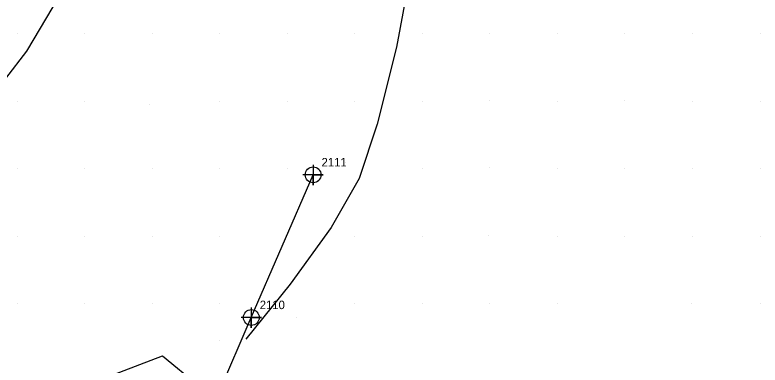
# Model space of a CAD drawing. Extents: x 2062781 to 2066835, y 358981 to 366501.
# Drawn here: x 2064250 to 2064470.6, y 361652.2 to 361755.8 of the extents above; entities that cross this region are included whole.
import ezdxf

# ---------------------------------------------------------------- set-up
doc = ezdxf.new("R2010")
doc.units = 0
for name, color, linetype in [('Exist DTM Breakline', 7, 'Continuous'), ('Exist DTM Breakline Cogo Number', 7, 'Continuous'), ('Exist DTM Breakline Cogo Point CELL', 7, 'Continuous'), ('PH Exist DTM Breakline', 7, 'Continuous'), ('PH Exist DTM Point', 7, 'Continuous')]:
    doc.layers.add(name, color=color, linetype=linetype)

msp = doc.modelspace()

# ---------------------------------------------------------------- linework, layer by layer
at = {"layer": 'Exist DTM Breakline'}
msp.add_lwpolyline([(2064211.92, 361508.57), (2064242.72, 361557.46), (2064262.04, 361578.64), (2064278.98, 361606.65), (2064285, 361628.9), (2064299.45, 361642.62), (2064310.38, 361643.91), (2064320.01, 361666.22), (2064338.31, 361708.44)], dxfattribs=at)
at = {"layer": 'Exist DTM Breakline Cogo Point CELL'}
for points in [[(2064338.31, 361711.44), (2064338.31, 361705.44), (2064338.31, 361708.44), (2064341.31, 361708.44), (2064335.31, 361708.44)], [(2064338.31, 361711.44), (2064338.31, 361705.44), (2064338.31, 361708.44), (2064341.31, 361708.44), (2064335.31, 361708.44)], [(2064338.31, 361711.44), (2064338.31, 361705.44), (2064338.31, 361708.44), (2064341.31, 361708.44), (2064335.31, 361708.44)], [(2064320.01, 361669.22), (2064320.01, 361663.22), (2064320.01, 361666.22), (2064323.01, 361666.22), (2064317.01, 361666.22)], [(2064320.01, 361669.22), (2064320.01, 361663.22), (2064320.01, 361666.22), (2064323.01, 361666.22), (2064317.01, 361666.22)], [(2064320.01, 361669.22), (2064320.01, 361663.22), (2064320.01, 361666.22), (2064323.01, 361666.22), (2064317.01, 361666.22)]]:
    msp.add_lwpolyline(points, dxfattribs=at)
for centre in [(2064338.31, 361708.44), (2064338.31, 361708.44), (2064338.31, 361708.44), (2064320.01, 361666.22), (2064320.01, 361666.22), (2064320.01, 361666.22)]:
    msp.add_circle(centre, 2.34, dxfattribs=at)
at = {"layer": 'PH Exist DTM Breakline'}
for points in [[(2064284.11, 361836.49), (2064284.24, 361836.01), (2064286.25, 361832.17), (2064287.7, 361828.99), (2064288.23, 361824.16), (2064290.83, 361816.85), (2064290.25, 361808.52), (2064287.43, 361797.59), (2064283.39, 361789.01), (2064278.56, 361782.76), (2064273.61, 361777.5), (2064267.04, 361768.03), (2064261.24, 361758.13), (2064253.47, 361745.07), (2064247.22, 361736.91)], [(2064367.79, 361772.3), (2064362.97, 361746.26), (2064357.25, 361723.49), (2064351.94, 361707.35), (2064343.68, 361692.85), (2064331.48, 361676.11), (2064318.44, 361659.84)], [(2064218.65, 361638.46), (2064234.01, 361624.32), (2064247.35, 361613.34), (2064259.26, 361629.82), (2064279.01, 361649.29), (2064293.71, 361654.92), (2064304.24, 361646.19), (2064305.97, 361645.17)]]:
    msp.add_lwpolyline(points, dxfattribs=at)
at = {"layer": 'PH Exist DTM Point'}
for p, q in [((2064250.65, 361750.27), (2064250.65, 361750.27)), ((2064270.65, 361750.27), (2064270.65, 361750.27)), ((2064290.63, 361750.24), (2064290.63, 361750.24)), ((2064310.65, 361750.27), (2064310.65, 361750.27)), ((2064330.65, 361750.27), (2064330.65, 361750.27)), ((2064350.65, 361750.27), (2064350.65, 361750.27)), ((2064370.65, 361750.27), (2064370.65, 361750.27)), ((2064390.43, 361750.39), (2064390.43, 361750.39)), ((2064410.65, 361750.27), (2064410.65, 361750.27)), ((2064430.61, 361750.29), (2064430.61, 361750.29)), ((2064450.65, 361750.27), (2064450.65, 361750.27)), ((2064470.65, 361750.27), (2064470.65, 361750.27)), ((2064250.65, 361730.27), (2064250.65, 361730.27)), ((2064270.65, 361730.27), (2064270.65, 361730.27)), ((2064310.65, 361730.27), (2064310.65, 361730.27)), ((2064330.65, 361730.27), (2064330.65, 361730.27)), ((2064350.65, 361730.27), (2064350.65, 361730.27)), ((2064390.47, 361730.32), (2064390.47, 361730.32)), ((2064410.65, 361730.27), (2064410.65, 361730.27)), ((2064430.44, 361730.42), (2064430.44, 361730.42)), ((2064450.65, 361730.27), (2064450.65, 361730.27)), ((2064470.65, 361730.27), (2064470.65, 361730.27)), ((2064289.95, 361729.36), (2064289.95, 361729.36)), ((2064370.63, 361730.24), (2064370.63, 361730.24)), ((2064347.93, 361712.03), (2064347.93, 361712.03)), ((2064390.52, 361710.5), (2064390.52, 361710.5)), ((2064250.65, 361710.27), (2064250.65, 361710.27)), ((2064270.65, 361710.27), (2064270.65, 361710.27)), ((2064290.65, 361710.27), (2064290.65, 361710.27)), ((2064310.65, 361710.27), (2064310.65, 361710.27)), ((2064330.65, 361710.27), (2064330.65, 361710.27)), ((2064370.65, 361710.27), (2064370.65, 361710.27)), ((2064410.65, 361710.27), (2064410.65, 361710.27)), ((2064430.55, 361710.32), (2064430.55, 361710.32)), ((2064450.65, 361710.27), (2064450.65, 361710.27)), ((2064470.65, 361710.27), (2064470.65, 361710.27)), ((2064250.65, 361690.27), (2064250.65, 361690.27)), ((2064270.65, 361690.27), (2064270.65, 361690.27)), ((2064290.65, 361690.27), (2064290.65, 361690.27)), ((2064310.65, 361690.27), (2064310.65, 361690.27)), ((2064350.65, 361690.27), (2064350.65, 361690.27)), ((2064370.65, 361690.27), (2064370.65, 361690.27)), ((2064390.35, 361690.46), (2064390.35, 361690.46)), ((2064410.65, 361690.27), (2064410.65, 361690.27)), ((2064430.65, 361690.27), (2064430.65, 361690.27)), ((2064450.65, 361690.27), (2064450.65, 361690.27)), ((2064470.65, 361690.27), (2064470.65, 361690.27)), ((2064250.65, 361670.27), (2064250.65, 361670.27)), ((2064270.65, 361670.27), (2064270.65, 361670.27)), ((2064290.65, 361670.27), (2064290.65, 361670.27)), ((2064310.65, 361670.27), (2064310.65, 361670.27)), ((2064350.65, 361670.27), (2064350.65, 361670.27)), ((2064370.65, 361670.27), (2064370.65, 361670.27)), ((2064390.65, 361670.27), (2064390.65, 361670.27)), ((2064410.65, 361670.27), (2064410.65, 361670.27)), ((2064450.27, 361670.39), (2064450.27, 361670.39)), ((2064470.65, 361670.27), (2064470.65, 361670.27)), ((2064333.27, 361666.12), (2064333.27, 361666.12)), ((2064310.5, 361659.36), (2064310.5, 361659.36))]:
    msp.add_line(p, q, dxfattribs=at)

# ---------------------------------------------------------------- texts
at = {"layer": 'Exist DTM Breakline Cogo Number'}
for s, p in [('2111', (2064340.81, 361710.94)), ('2111', (2064340.81, 361710.94)), ('2111', (2064340.81, 361710.94)), ('2110', (2064322.51, 361668.72)), ('2110', (2064322.51, 361668.72)), ('2110', (2064322.51, 361668.72))]:
    msp.add_text(s, height=2.5, dxfattribs=at).set_placement(p)

doc.saveas('drawing.dxf')
